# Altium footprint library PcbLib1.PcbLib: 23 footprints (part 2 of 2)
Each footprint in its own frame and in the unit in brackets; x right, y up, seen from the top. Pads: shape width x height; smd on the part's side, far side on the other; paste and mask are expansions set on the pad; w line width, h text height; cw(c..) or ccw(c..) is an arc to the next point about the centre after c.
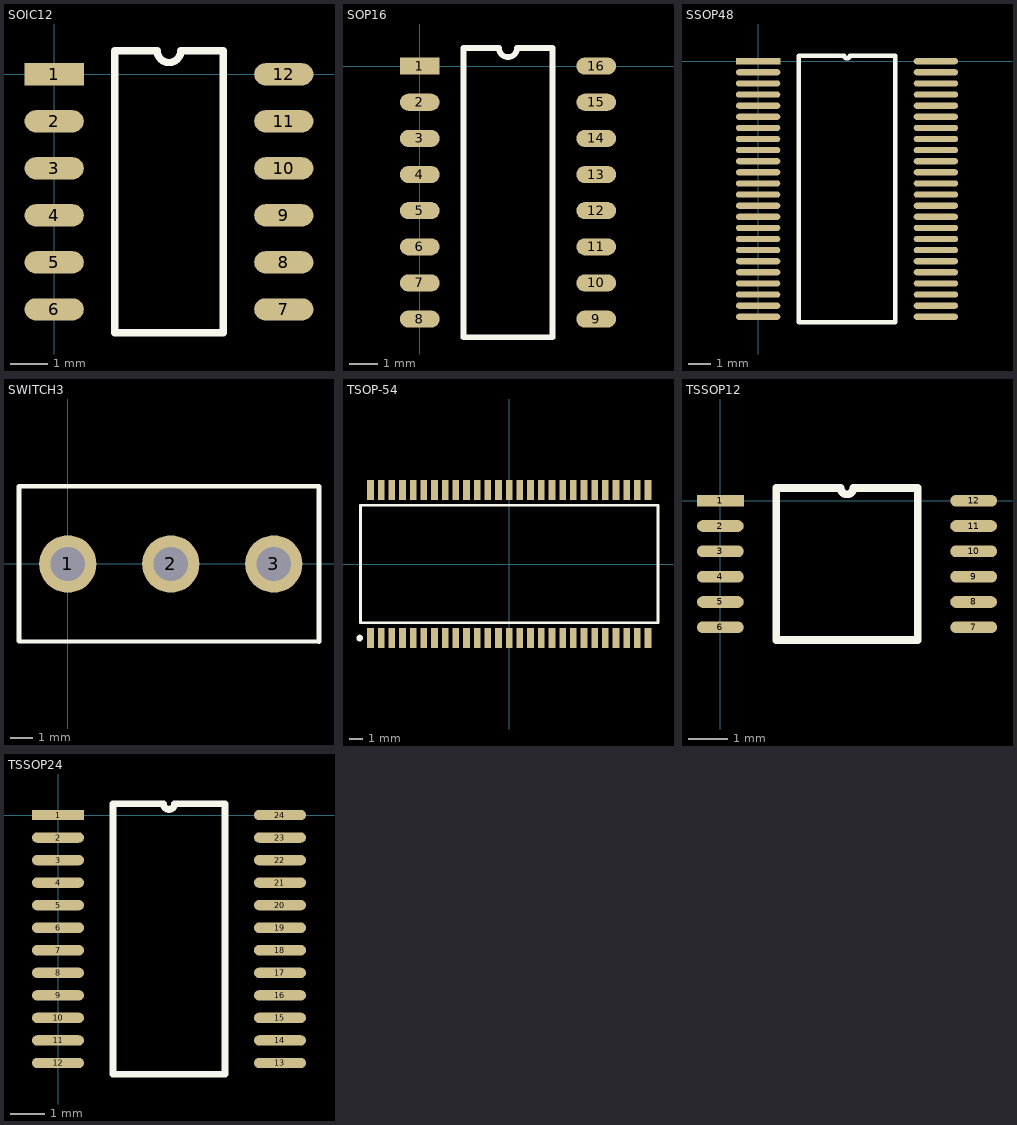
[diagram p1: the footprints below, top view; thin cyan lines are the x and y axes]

## SOIC12 [mm] "for MAX9122/9121"
pads (12):
  rect 1.6x0.6 smd: 1(0,0)
  oval 1.6x0.6 smd: 2(0,-1.27) 3(0,-2.54) 4(0,-3.81) 5(0,-5.08) 6(0,-6.35) 7(6.2,-6.35) 8(6.2,-5.08) 9(6.2,-3.81) 10(6.2,-2.54) 11(6.2,-1.27) 12(6.2,0)
Top Overlay:
  lines w0.2: 1.635,-6.985 4.565,-6.985 4.565,0.635 3.417,0.635 cw(c3.1,0.635) 2.782,0.635 1.635,0.635 1.635,-6.985

## SOP16 [mm] "for MAX9122"
pads (16):
  rect 1.4x0.6 smd: 1(0,0)
  oval 1.4x0.6 smd: 2(0,-1.27) 3(0,-2.54) 4(0,-3.81) 5(0,-5.08) 6(0,-6.35) 7(0,-7.62) 8(0,-8.89) 9(6.2,-8.89) 10(6.2,-7.62) 11(6.2,-6.35) 12(6.2,-5.08) 13(6.2,-3.81) 14(6.2,-2.54) 15(6.2,-1.27) 16(6.2,0)
Top Overlay:
  lines w0.2: 1.535,-9.525 4.665,-9.525 4.665,0.635 3.417,0.635 cw(c3.1,0.635) 2.782,0.635 1.535,0.635 1.535,-9.525

## SSOP48 [mm]
pads (48):
  rect 2x0.28 smd: 1(0,0)
  oval 2x0.28 smd: 2(0,-0.5) 3(0,-1) 4(0,-1.5) 5(0,-2) 6(0,-2.5) 7(0,-3) 8(0,-3.5) 9(0,-4) 10(0,-4.5) 11(0,-5) 12(0,-5.5) 13(0,-6) 14(0,-6.5) 15(0,-7) 16(0,-7.5) 17(0,-8) 18(0,-8.5) 19(0,-9) 20(0,-9.5) 21(0,-10) 22(0,-10.5) 23(0,-11) 24(0,-11.5) 25(8,-11.5) 26(8,-11) 27(8,-10.5) 28(8,-10) 29(8,-9.5) 30(8,-9) 31(8,-8.5) 32(8,-8) 33(8,-7.5) 34(8,-7) 35(8,-6.5) 36(8,-6) 37(8,-5.5) 38(8,-5) 39(8,-4.5) 40(8,-4) 41(8,-3.5) 42(8,-3) 43(8,-2.5) 44(8,-2) 45(8,-1.5) 46(8,-1) 47(8,-0.5) 48(8,0)
Top Overlay:
  lines w0.2: 1.835,-11.75 1.835,0.25 3.875,0.25 ccw(c4,0.25) 4.125,0.25 6.165,0.25 6.165,-11.75 1.835,-11.75

## SWITCH3 [mm]
pads (3):
  round 2.5 hole 1.5: 1(0,0) 2(4.5,0) 3(9,0)
Top Overlay:
  lines w0.203: -2.134,1.346 -2.134,3.404 10.973,3.4 10.973,-3.404 -2.134,-3.378 -2.134,1.626

## TSOP-54 [mm]
pads (54):
  rect 0.5x1.5 smd: 1(-10.4,-5.55) 2(-9.6,-5.55) 3(-8.8,-5.55) 4(-8,-5.55) 5(-7.2,-5.55) 6(-6.4,-5.55) 7(-5.6,-5.55) 8(-4.8,-5.55) 9(-4,-5.55) 10(-3.2,-5.55) 11(-2.4,-5.55) 12(-1.6,-5.55) 13(-0.8,-5.55) 14(0,-5.55) 15(0.8,-5.55) 16(1.6,-5.55) 17(2.4,-5.55) 18(3.2,-5.55) 19(4,-5.55) 20(4.8,-5.55) 21(5.6,-5.55) 22(6.4,-5.55) 23(7.2,-5.55) 24(8,-5.55) 25(8.8,-5.55) 26(9.6,-5.55) 27(10.4,-5.55) 28(10.4,5.55) 29(9.6,5.55) 30(8.8,5.55) 31(8,5.55) 32(7.2,5.55) 33(6.4,5.55) 34(5.6,5.55) 35(4.8,5.55) 36(4,5.55) 37(3.2,5.55) 38(2.4,5.55) 39(1.6,5.55) 40(0.8,5.55) 41(0,5.55) 42(-0.8,5.55) 43(-1.6,5.55) 44(-2.4,5.55) 45(-3.2,5.55) 46(-4,5.55) 47(-4.8,5.55) 48(-5.6,5.55) 49(-6.4,5.55) 50(-7.2,5.55) 51(-8,5.55) 52(-8.8,5.55) 53(-9.6,5.55) 54(-10.4,5.55)
Top Overlay:
  circle w0.25: c-11.21,-5.55 r0.125
  lines w0.2: -11.15,-4.4 11.15,-4.4 11.15,4.4 -11.15,4.4 -11.15,-0.635 -11.15,-4.4

## TSSOP12 [mm] "for MAX9122"
pads (12):
  rect 1.2x0.3 smd: 1(0,0)
  oval 1.2x0.3 smd: 2(0,-0.65) 3(0,-1.3) 4(0,-1.95) 5(0,-2.6) 6(0,-3.25) 7(6.5,-3.25) 8(6.5,-2.6) 9(6.5,-1.95) 10(6.5,-1.3) 11(6.5,-0.65) 12(6.5,0)
Top Overlay:
  lines w0.2: 1.435,-3.575 1.435,0.325 3.087,0.325 ccw(c3.25,0.325) 3.412,0.325 5.065,0.325 5.065,-3.575 1.435,-3.575

## TSSOP24 [mm] "for QS3861"
pads (24):
  rect 1.5x0.3 smd: 1(0,0)
  oval 1.5x0.3 smd: 2(0,-0.65) 3(0,-1.3) 4(0,-1.95) 5(0,-2.6) 6(0,-3.25) 7(0,-3.9) 8(0,-4.55) 9(0,-5.2) 10(0,-5.85) 11(0,-6.5) 12(0,-7.15) 13(6.4,-7.15) 14(6.4,-6.5) 15(6.4,-5.85) 16(6.4,-5.2) 17(6.4,-4.55) 18(6.4,-3.9) 19(6.4,-3.25) 20(6.4,-2.6) 21(6.4,-1.95) 22(6.4,-1.3) 23(6.4,-0.65) 24(6.4,0)
Top Overlay:
  lines w0.2: 1.585,-7.475 1.585,0.325 3.037,0.325 ccw(c3.2,0.325) 3.362,0.325 4.815,0.325 4.815,-7.475 1.585,-7.475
